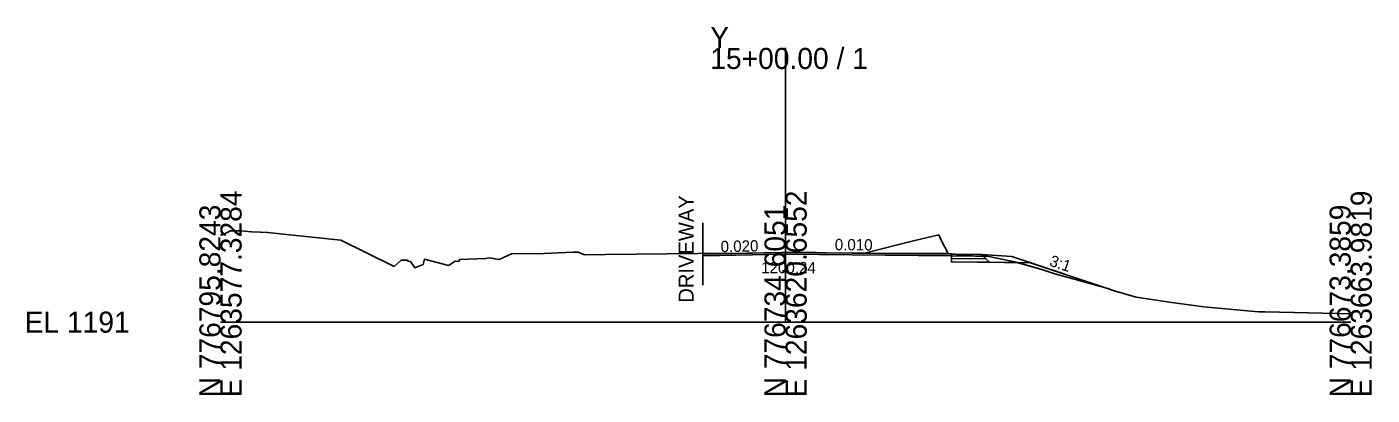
# Model space of a CAD drawing. Extents: x -51 to 1263719, y -10 to 776845.
# Drawn here: x 1124.3 to 1302.8, y -9.7 to 39.2 of the extents above; entities that cross this region are included whole.
import ezdxf

# ---------------------------------------------------------------- set-up
doc = ezdxf.new("R2010")
doc.units = 0
for name, color, linetype in [('Exist Cross Section Cell', 7, 'Continuous'), ('Exist XS Center Line Elevation Label', 7, 'Continuous'), ('Exist XS Ground Line', 7, 'Continuous'), ('Prop CMT Shear Line', 7, 'Continuous'), ('Prop CMT Shld Paved Course 1', 7, 'Continuous'), ('Prop CMT Shld Paved Course 2', 7, 'Continuous'), ('Prop CMT Shld Paved Course 4', 7, 'Continuous'), ('Prop CMT Subgrade Earthwork', 7, 'Continuous'), ('Prop XS Earthwork Shape', 7, 'Continuous'), ('Prop XS Finish Grade', 7, 'Continuous'), ('Prop XS SE Text', 7, 'Continuous'), ('Prop XS Side Slope Text', 7, 'Continuous'), ('Scratch_Level_2', 7, 'Continuous')]:
    doc.layers.add(name, color=color, linetype=linetype)

msp = doc.modelspace()

# ---------------------------------------------------------------- linework, layer by layer
at = {"layer": 'Exist Cross Section Cell'}
for p, q in [((1225, 0), (1225, 36.42)), ((1150, 0), (1225, 0)), ((1225, 0), (1300, 0))]:
    msp.add_line(p, q, dxfattribs=at)
at = {"layer": 'Exist XS Ground Line'}
msp.add_lwpolyline([(1150, 11.59), (1150.26, 11.58), (1150.99, 11.95), (1151.32, 12.12), (1151.87, 12.13), (1152.68, 12.14), (1154.11, 12.01), (1155.31, 11.96), (1156.26, 11.92), (1165.99, 10.9), (1173.03, 7.41), (1173.97, 8.23), (1174.82, 8.22), (1174.9, 8.08), (1175.22, 8.06), (1175.78, 7.23), (1176.89, 7.67), (1177.06, 8.36), (1179.58, 7.72), (1180.28, 7.53), (1181.14, 8.1), (1181.65, 8.06), (1181.74, 8.31), (1185.19, 8.45), (1185.67, 8.55), (1186.99, 8.34), (1188.7, 9.13), (1191.99, 9.07), (1196.82, 9.29), (1197.48, 9.31), (1198.33, 8.93), (1199.51, 8.97), (1200.41, 8.96), (1201.06, 8.97), (1213.34, 9.13), (1219.85, 9.17), (1224.43, 9.24), (1225, 9.24), (1228.24, 9.24), (1229.04, 9.24), (1230.06, 9.22), (1235.44, 9.15), (1246.57, 9.1), (1250.3, 8.75), (1251.74, 8.76), (1255.22, 8.07), (1259.02, 6.98), (1260.73, 6.42), (1264.76, 5.33), (1267.75, 4.45), (1268.48, 4.2), (1271.53, 3.3), (1275.96, 2.66), (1280.53, 2.05), (1287.78, 1.39), (1288.66, 1.35), (1294.41, 1.23), (1300, 1.12)], dxfattribs=at)
at = {"layer": 'Prop CMT Shear Line'}
msp.add_line((1214, 13.18), (1214, 4.9), dxfattribs=at)
at = {"layer": 'Prop CMT Shld Paved Course 1'}
for p, q in [((1214, 8.79), (1225, 9.01)), ((1225, 9.01), (1247.01, 8.79)), ((1247.01, 8.79), (1247, 9.04)), ((1251, 9), (1251.26, 8.75)), ((1247.01, 8.79), (1251.26, 8.75))]:
    msp.add_line(p, q, dxfattribs=at)
at = {"layer": 'Prop CMT Shld Paved Course 2'}
for p, q in [((1247.01, 8.46), (1247.01, 8.79)), ((1247.01, 8.46), (1251.59, 8.41)), ((1251.59, 8.41), (1251.26, 8.75))]:
    msp.add_line(p, q, dxfattribs=at)
at = {"layer": 'Prop CMT Shld Paved Course 4'}
for p, q in [((1247.01, 8), (1247.01, 8.46)), ((1247.01, 8), (1257.49, 7.89)), ((1251.59, 8.41), (1252.06, 7.95))]:
    msp.add_line(p, q, dxfattribs=at)
at = {"layer": 'Prop CMT Subgrade Earthwork'}
for q in [(1247, 9.02), (1257.49, 7.89)]:
    msp.add_line((1247.01, 8), q, dxfattribs=at)
at = {"layer": 'Prop XS Earthwork Shape'}
for points in [[(1245.7, 10.82), (1246.57, 9.1), (1247.24, 9.04), (1247, 9.04), (1235.46, 9.16), (1242.16, 10.83), (1245.33, 11.59)], [(1226.93, 9.24), (1233.9, 9.17), (1235.44, 9.15), (1235.46, 9.16), (1247, 9.04), (1247, 9.02), (1247.01, 8.79), (1225, 9.01), (1214, 8.79), (1214, 9.04), (1222.76, 9.22), (1224.43, 9.24), (1225, 9.24)], [(1226.93, 9.24), (1233.9, 9.17), (1230.06, 9.22), (1229.04, 9.24), (1228.24, 9.24)], [(1247, 9.04), (1247.24, 9.04), (1250.17, 8.76), (1247.01, 8.79), (1247, 9.02)], [(1250.3, 8.75), (1250.77, 8.75), (1251.26, 8.75), (1251.59, 8.41), (1247.01, 8.46), (1247.01, 8.79), (1250.17, 8.76)], [(1247.01, 8.46), (1251.59, 8.41), (1252.06, 7.95), (1247.01, 8)], [(1251.25, 8.76), (1251.26, 8.75), (1250.77, 8.75)], [(1251.25, 8.76), (1251.26, 8.75), (1251.59, 8.41), (1252.06, 7.95), (1255.79, 7.91), (1255.22, 8.07), (1251.74, 8.76)], [(1268.48, 4.2), (1269.19, 3.99), (1257.49, 7.89), (1255.79, 7.91), (1259.02, 6.98), (1260.73, 6.42), (1264.76, 5.33), (1267.75, 4.45)]]:
    msp.add_lwpolyline(points, close=True, dxfattribs=at)
at = {"layer": 'Prop XS Finish Grade'}
for p, q in [((1214, 9.04), (1225, 9.26)), ((1214, 9.04), (1214, 8.79)), ((1225, 9.26), (1247, 9.04)), ((1247, 9.04), (1251, 9)), ((1251, 9), (1255.01, 8.72)), ((1255.01, 8.72), (1269.19, 3.99))]:
    msp.add_line(p, q, dxfattribs=at)
at = {"layer": 'Scratch_Level_2'}
msp.add_line((1255.01, 8.72), (1255.34, 8.61), dxfattribs=at)

# ---------------------------------------------------------------- texts
at = {"layer": 'Exist Cross Section Cell'}
for s, p in [('Y', (1215, 36.42)), ('15+00.00 / 1', (1215, 33.62)), ('EL 1191', (1124, -1.4))]:
    msp.add_text(s, height=2.8, dxfattribs=at).set_placement(p)
for s, p in [('E 1263577.3284', (1152.8, -10)), ('E 1263620.6552', (1227.8, -10)), ('E 1263663.9819', (1302.8, -10)), ('N 776795.8243', (1150, -10)), ('N 776734.6051', (1225, -10)), ('N 776673.3859', (1300, -10))]:
    msp.add_text(s, height=2.8, rotation=90, dxfattribs=at).set_placement(p)
at = {"layer": 'Exist XS Center Line Elevation Label'}
msp.add_text('1200.24', height=1.5, dxfattribs=at).set_placement((1221.76, 6.49))
at = {"layer": 'Prop CMT Shear Line'}
msp.add_text('DRIVEWAY', height=2, rotation=90, dxfattribs=at).set_placement((1212.8, 2.58))
at = {"layer": 'Prop XS SE Text'}
for s, rotation, p in [('0.020', 1.1458, (1216.39, 9.29)), ('0.010', 359.4271, (1231.52, 9.56))]:
    msp.add_text(s, height=1.5, rotation=rotation, dxfattribs=at).set_placement(p)
at = {"layer": 'Prop XS Side Slope Text'}
msp.add_text('3:1', height=1.5, rotation=341.5651, dxfattribs=at).set_placement((1259.92, 7.52))

doc.saveas('drawing.dxf')
